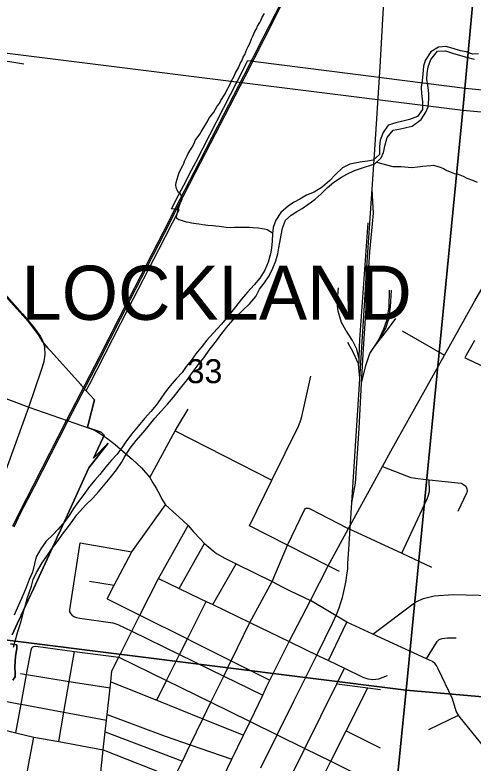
# Model space of a CAD drawing. Extents: x 0 to 34, y -3.9 to 26.2.
# Drawn here: x 3.391 to 4.192, y 19.139 to 20.448 of the extents above; entities that cross this region are included whole.
import ezdxf

# ---------------------------------------------------------------- set-up
doc = ezdxf.new("R2010")
doc.units = 0
for name, color, linetype in [('GM_X_City_Street', 7, 'Continuous'), ('GM_X_Corporation', 7, 'Continuous'), ('GM_X_Corporation_Text', 7, 'Continuous'), ('GM_X_County_Road', 7, 'Continuous'), ('GM_X_Interchange_Ramps', 7, 'Continuous'), ('GM_X_Minor_River', 7, 'Continuous'), ('GM_X_Rail_Line', 7, 'Continuous'), ('GM_X_Section', 7, 'Continuous'), ('GM_X_Section_Text', 7, 'Continuous'), ('GM_X_State_Shield', 7, 'Continuous'), ('GM_X_US_Route', 7, 'Continuous')]:
    doc.layers.add(name, color=color, linetype=linetype)

msp = doc.modelspace()

# ---------------------------------------------------------------- linework, layer by layer
at = {"layer": 'GM_X_City_Street'}
for p, q in [((4.0681, 19.8952), (4.1418, 19.8529)), ((3.3597, 19.61), (3.4148, 19.7617)), ((3.6706, 19.7205), (3.84, 19.6339)), ((3.5049, 19.5244), (3.5948, 19.5084)), ((3.6777, 19.4447), (3.722, 19.5232)), ((3.7366, 19.4163), (3.7778, 19.4875)), ((3.521, 19.4572), (3.5642, 19.4502)), ((3.9392, 19.3185), (3.9713, 19.3857)), ((4.1147, 19.1976), (4.1666, 19.2228)), ((3.5484, 19.1936), (3.6834, 19.1427)), ((3.9699, 19.1953), (4.0293, 19.1657))]:
    msp.add_line(p, q, dxfattribs=at)
for points in [[(3.4148, 19.7617), (3.4368, 19.8271), (3.4416, 19.8416), (3.4433, 19.8548), (3.4426, 19.866)], [(3.8011, 19.5541), (3.84, 19.6339), (3.8864, 19.7288), (3.8912, 19.7408), (3.8955, 19.7585), (3.9083, 19.8163)], [(3.3007, 19.802), (3.3616, 19.7815), (3.4148, 19.7617)], [(3.4148, 19.7617), (3.5219, 19.7242), (3.5312, 19.7208), (3.5369, 19.7176), (3.5437, 19.7128), (3.5509, 19.7081)], [(3.6266, 19.6385), (3.6706, 19.7205), (3.6764, 19.7301), (3.6933, 19.7582)], [(3.5509, 19.7081), (3.5661, 19.6967), (3.5799, 19.6842), (3.5955, 19.6711), (3.6118, 19.6559), (3.6266, 19.6385), (3.632, 19.6297), (3.6378, 19.6199), (3.6432, 19.6094), (3.6473, 19.6006), (3.6541, 19.5911), (3.6669, 19.579), (3.6772, 19.5701), (3.6933, 19.5547), (3.7028, 19.5438), (3.7144, 19.5316), (3.722, 19.5232), (3.7372, 19.5102), (3.7433, 19.5055), (3.7575, 19.4979), (3.7778, 19.4875), (3.8403, 19.4566), (3.857, 19.4482)], [(4.0332, 19.6577), (4.0757, 19.6417), (4.0832, 19.6389), (4.0953, 19.637), (4.115, 19.6348), (4.1709, 19.6286), (4.1735, 19.6276), (4.1754, 19.6265), (4.1776, 19.6249), (4.1791, 19.6234), (4.1803, 19.6209), (4.1809, 19.6188), (4.1813, 19.6157), (4.1811, 19.6127), (4.1806, 19.6112), (4.1651, 19.579)], [(4.067, 19.5061), (4.1114, 19.6017), (4.1131, 19.6058), (4.1159, 19.6141), (4.115, 19.6348)], [(3.5517, 19.4263), (3.5642, 19.4502), (3.5948, 19.5084), (3.6541, 19.5911)], [(3.7643, 19.3091), (3.7687, 19.318), (3.8013, 19.3851), (3.8403, 19.4566), (3.8671, 19.5205), (3.897, 19.5819), (3.8983, 19.5837), (3.8991, 19.5845), (3.8997, 19.5849)], [(3.8997, 19.5849), (3.9018, 19.5853), (3.9029, 19.5853), (3.9036, 19.5851), (3.9069, 19.584), (3.9723, 19.5501), (3.9742, 19.5493), (4.067, 19.5061), (4.119, 19.4819)], [(3.5449, 19.1623), (3.5484, 19.1936), (3.5507, 19.2144), (3.5518, 19.2241), (3.557, 19.2709), (3.5581, 19.2811), (3.5602, 19.3004), (3.5723, 19.3244), (3.5952, 19.3698), (3.6093, 19.3976), (3.6418, 19.4621), (3.6933, 19.5547)], [(3.9583, 19.474), (3.9387, 19.484), (3.8671, 19.5205), (3.8011, 19.5541)], [(3.491, 19.3972), (3.489, 19.4), (3.4869, 19.4036), (3.4866, 19.4054), (3.4865, 19.4073), (3.5049, 19.5244)], [(3.6418, 19.4621), (3.6777, 19.4447), (3.714, 19.4272), (3.7249, 19.4219), (3.7366, 19.4163), (3.8013, 19.3851), (3.8701, 19.3518), (3.9215, 19.327), (3.9392, 19.3185), (3.9672, 19.305), (3.9991, 19.2895), (4.0078, 19.2866), (4.0165, 19.2856), (4.0271, 19.2865), (4.0421, 19.2922)], [(3.857, 19.4482), (3.8721, 19.4407), (3.9077, 19.4237)], [(3.5517, 19.4263), (3.6093, 19.3976), (3.6922, 19.3562), (3.699, 19.3528), (3.7432, 19.3307)], [(4.0164, 19.3649), (4.0916, 19.4215), (4.1051, 19.4272), (4.1238, 19.4316), (4.1572, 19.4341), (4.2023, 19.4327), (4.2372, 19.4316), (4.2485, 19.4287), (4.2785, 19.4187), (4.4519, 19.3613), (4.4663, 19.3606), (4.4834, 19.3624), (4.5054, 19.3622), (4.5311, 19.3555), (4.5363, 19.3541), (4.5575, 19.3517), (4.576, 19.3508), (4.5859, 19.3508), (4.6386, 19.3507), (4.6468, 19.3506)], [(3.6386, 19.2489), (3.6558, 19.2834), (3.6786, 19.329), (3.6922, 19.3562), (3.7249, 19.4219)], [(3.491, 19.3972), (3.4948, 19.395), (3.4967, 19.3941), (3.4985, 19.3936), (3.5041, 19.3926), (3.562, 19.3847), (3.5707, 19.3818), (3.5952, 19.3698), (3.6786, 19.329), (3.7557, 19.2914), (3.8239, 19.258)], [(4.1102, 19.3217), (4.1289, 19.3517), (4.1311, 19.3542), (4.1328, 19.3554), (4.138, 19.3573), (4.1473, 19.3585), (4.1621, 19.3585)], [(3.3923, 19.1922), (3.4014, 19.2419), (3.4109, 19.2939), (3.4187, 19.3368), (3.4201, 19.3407), (3.4221, 19.3425)], [(3.4221, 19.3425), (3.4236, 19.3432), (3.4272, 19.3434), (3.4948, 19.3345), (3.5723, 19.3244), (3.6558, 19.2834), (3.7334, 19.2455), (3.8018, 19.2119), (3.8977, 19.1646), (3.9431, 19.1423), (3.9923, 19.118), (4.0492, 19.09), (4.0704, 19.0795)], [(3.4673, 19.1766), (3.4763, 19.2281), (3.4857, 19.2821), (3.4948, 19.3345)], [(3.7432, 19.3307), (3.7678, 19.3184), (3.7687, 19.318), (3.8366, 19.2841)], [(3.6691, 19.1134), (3.6834, 19.1427), (3.6972, 19.1712), (3.7193, 19.2166), (3.7334, 19.2455), (3.7557, 19.2914), (3.7621, 19.3046), (3.7643, 19.3091)], [(3.4001, 19.2956), (3.4109, 19.2939), (3.4857, 19.2821), (3.557, 19.2709)], [(3.8977, 19.1646), (3.9536, 19.2776), (3.9672, 19.305)], [(3.5581, 19.2811), (3.6386, 19.2489), (3.7193, 19.2166), (3.7904, 19.1882)], [(3.8388, 18.935), (3.8803, 19.0174), (3.9103, 19.0771), (3.9431, 19.1423), (3.9438, 19.1437), (3.9699, 19.1953), (4.0078, 19.2707)], [(3.9536, 19.2776), (4.0078, 19.2707), (4.0301, 19.2678)], [(3.367, 19.2483), (3.3976, 19.2426), (3.4014, 19.2419), (3.4763, 19.2281), (3.5507, 19.2144)], [(3.5518, 19.2241), (3.6533, 19.1863), (3.6972, 19.1712), (3.7702, 19.146)], [(3.4053, 19.0874), (3.4144, 19.1356), (3.4236, 19.1847)], [(3.4926, 18.5849), (3.5025, 18.6997), (3.5108, 18.7976), (3.5115, 18.8047), (3.5134, 18.828), (3.5168, 18.8676), (3.5237, 18.9295), (3.5302, 19.011), (3.5325, 19.0346), (3.5353, 19.0637), (3.5382, 19.0938), (3.54, 19.1119), (3.5417, 19.1292), (3.5449, 19.1623)], [(3.8356, 19.0391), (3.8965, 19.1621), (3.8977, 19.1646)]]:
    msp.add_lwpolyline(points, dxfattribs=at)
at = {"layer": 'GM_X_Corporation'}
for points in [[(3.386, 19.3632), (3.3947, 19.3825), (3.4015, 19.3975), (3.4016, 19.3976), (3.4016, 19.3977), (3.418, 19.4328), (3.4201, 19.4375), (3.4364, 19.4729), (3.4503, 19.5033), (3.4568, 19.5176), (3.4633, 19.5316), (3.4653, 19.536), (3.4673, 19.5404), (3.4853, 19.5796), (3.5201, 19.6554), (3.5535, 19.6989), (3.5281, 19.6728), (3.5441, 19.7076), (3.5465, 19.7129), (3.5412, 19.7178), (3.5272, 19.7228), (3.5176, 19.7262), (3.5189, 19.7315), (3.5297, 19.7747), (3.5154, 19.7906), (3.5182, 19.796), (3.521, 19.8014), (3.5895, 19.9348), (3.6422, 20.0377), (3.6779, 20.1072), (3.6644, 20.1087), (3.6763, 20.1314), (3.691, 20.1603), (3.6961, 20.1701), (3.7071, 20.1905), (3.7799, 20.3326), (3.7981, 20.3683), (3.8113, 20.3666), (4.0185, 20.3402), (4.036, 20.338), (4.1782, 20.3198), (4.2502, 20.3128)], [(3.3557, 19.9761), (3.4101, 19.9157), (3.4153, 19.9092), (3.4298, 19.8903), (3.4353, 19.882), (3.4382, 19.8768), (3.4483, 19.8653), (3.4534, 19.8597), (3.5053, 19.802), (3.5066, 19.8005), (3.5154, 19.7906), (3.5297, 19.7747), (3.5189, 19.7315), (3.5176, 19.7264), (3.5176, 19.7262), (3.5272, 19.7228), (3.5412, 19.7178), (3.5465, 19.7129), (3.5441, 19.7076), (3.5281, 19.6728), (3.5535, 19.6989), (3.5201, 19.6554), (3.4853, 19.5796), (3.4673, 19.5404), (3.4653, 19.536), (3.4633, 19.5316), (3.4568, 19.5176), (3.4503, 19.5033), (3.4364, 19.4729), (3.4201, 19.4375), (3.418, 19.4328), (3.4016, 19.3977), (3.4016, 19.3976), (3.4015, 19.3975), (3.3947, 19.3825), (3.386, 19.3632)], [(4.1944, 19.8782), (4.1892, 19.8691), (4.1846, 19.8609), (4.1799, 19.8526), (4.1773, 19.8481), (4.179, 19.8473), (4.2295, 19.8237)], [(3.3903, 19.3062), (3.3908, 19.3174), (3.3918, 19.3255), (3.3918, 19.3256), (3.3928, 19.333), (3.3937, 19.3392), (3.3939, 19.3402), (3.3941, 19.3459), (3.3826, 19.3475)], [(3.3826, 19.3475), (3.3941, 19.3459), (3.3939, 19.3402), (3.3937, 19.3392), (3.3928, 19.333), (3.3918, 19.3256), (3.3918, 19.3255), (3.3908, 19.3174), (3.3903, 19.3062)], [(3.3872, 19.2843), (3.3911, 19.29), (3.3908, 19.2967), (3.3903, 19.3061)], [(3.3903, 19.3061), (3.3908, 19.2967), (3.3911, 19.29), (3.3872, 19.2843)]]:
    msp.add_lwpolyline(points, dxfattribs=at)
at = {"layer": 'GM_X_County_Road'}
for points in [[(3.2665, 20.3824), (3.3049, 20.3771), (3.3854, 20.3661), (3.4059, 20.3627)], [(3.249, 20.0295), (3.2583, 20.0286), (3.2683, 20.0273), (3.2804, 20.0244), (3.2873, 20.0228), (3.3037, 20.0165), (3.3175, 20.0101), (3.3318, 20.0009), (3.343, 19.9918), (3.3578, 19.9767), (3.363, 19.9705), (3.404, 19.9249), (3.4226, 19.9032), (3.4351, 19.8853), (3.4392, 19.8768), (3.4426, 19.866)], [(4.531, 18.7211), (4.5289, 18.7386), (4.5326, 18.7785), (4.5323, 18.7842), (4.5313, 18.7911), (4.5289, 18.798), (4.5251, 18.8049), (4.5234, 18.8071), (4.4853, 18.8456), (4.4237, 18.9101), (4.3697, 18.9768), (4.2658, 19.0997), (4.169, 19.2187), (4.1666, 19.2228), (4.1624, 19.2298), (4.1556, 19.2516), (4.1308, 19.3038), (4.1279, 19.3099), (4.1253, 19.3129), (4.1209, 19.3168), (4.1102, 19.3217), (4.0164, 19.3649), (3.9713, 19.3857), (3.9077, 19.4237)], [(3.3672, 19.1987), (3.3923, 19.1922), (3.4236, 19.1847), (3.4673, 19.1766), (3.5449, 19.1623), (3.6691, 19.1134), (3.6849, 19.1072), (3.741, 19.0851), (3.8356, 19.0391), (3.8803, 19.0174), (3.8891, 19.0131)]]:
    msp.add_lwpolyline(points, dxfattribs=at)
at = {"layer": 'GM_X_Interchange_Ramps'}
for points in [[(3.3557, 19.9761), (3.4101, 19.9157), (3.4153, 19.9092), (3.4298, 19.8903), (3.4353, 19.882), (3.4382, 19.8768), (3.4483, 19.8653), (3.4534, 19.8597), (3.5053, 19.802), (3.5066, 19.8005), (3.5154, 19.7906), (3.5182, 19.796), (3.5182, 19.796), (3.521, 19.8014), (3.5895, 19.9348), (3.6422, 20.0377), (3.6779, 20.1072), (3.6644, 20.1087), (3.6763, 20.1314), (3.691, 20.1603), (3.6961, 20.17), (3.7071, 20.1905), (3.7799, 20.3326), (3.7981, 20.3683), (3.8113, 20.3666), (4.0185, 20.3402), (4.036, 20.338), (4.1782, 20.3198), (4.2502, 20.3128)], [(4.1944, 19.8782), (4.1892, 19.8691), (4.1846, 19.8609), (4.1799, 19.8526), (4.1773, 19.8481), (4.179, 19.8473), (4.2295, 19.8237)]]:
    msp.add_lwpolyline(points, dxfattribs=at)
at = {"layer": 'GM_X_Minor_River'}
for points in [[(3.8408, 20.0661), (3.8317, 20.072), (3.8268, 20.0733), (3.823, 20.0739), (3.8166, 20.0749), (3.8071, 20.0753), (3.8007, 20.0759), (3.7965, 20.0761), (3.7885, 20.0761), (3.7836, 20.0759), (3.7748, 20.0759), (3.768, 20.0758), (3.76, 20.0761), (3.7562, 20.0766), (3.7521, 20.0772), (3.7475, 20.0778), (3.7418, 20.0784), (3.7366, 20.079), (3.7278, 20.0797), (3.7241, 20.0802), (3.7184, 20.0809), (3.7123, 20.0819), (3.7078, 20.0824), (3.6995, 20.0839), (3.695, 20.0849), (3.6904, 20.0854), (3.6822, 20.0881), (3.6773, 20.0894), (3.6736, 20.0918), (3.6734, 20.096), (3.6769, 20.1092), (3.6783, 20.1145), (3.6805, 20.1212), (3.6829, 20.1249), (3.6827, 20.1302), (3.6802, 20.1345), (3.6765, 20.1373), (3.6744, 20.1416), (3.6727, 20.1459), (3.6721, 20.1508), (3.6727, 20.1546), (3.6779, 20.1726), (3.6837, 20.1834), (3.6857, 20.1879), (3.6871, 20.1924), (3.692, 20.2017), (3.6937, 20.2054), (3.7006, 20.2169), (3.7038, 20.2229), (3.7056, 20.2285), (3.714, 20.2392), (3.7161, 20.2433), (3.7246, 20.257), (3.7278, 20.2626), (3.7295, 20.267), (3.7387, 20.2781), (3.7444, 20.2885), (3.7484, 20.2933), (3.7509, 20.2985), (3.7582, 20.31), (3.7599, 20.3141), (3.7664, 20.326), (3.7681, 20.3304), (3.7747, 20.342), (3.776, 20.3457), (3.7821, 20.3569), (3.7846, 20.3632), (3.7875, 20.368), (3.7896, 20.3744), (3.7928, 20.3788), (3.7963, 20.3882), (3.7987, 20.393), (3.8012, 20.3983), (3.8042, 20.4061), (3.8058, 20.4099), (3.8087, 20.4151), (3.81, 20.4192), (3.8129, 20.424), (3.8146, 20.4285), (3.819, 20.4348), (3.8207, 20.4385), (3.8228, 20.4441), (3.8272, 20.4508)], [(4.2014, 20.3801), (4.1916, 20.3796), (4.1795, 20.3832), (4.1697, 20.3853), (4.1572, 20.3893), (4.1444, 20.393), (4.1315, 20.3917), (4.1177, 20.3832), (4.1083, 20.3682), (4.1054, 20.3584), (4.104, 20.3451), (4.1027, 20.3329), (4.1013, 20.3219), (4.1019, 20.3102), (4.1035, 20.2964), (4.1032, 20.2828), (4.0947, 20.2704), (4.0809, 20.2653), (4.0691, 20.2621), (4.0569, 20.2593), (4.0435, 20.2554), (4.0349, 20.2422), (4.0294, 20.229), (4.0284, 20.2176), (4.0282, 20.204), (4.017, 20.1939), (4.0071, 20.1922), (3.9976, 20.1912), (3.988, 20.1895), (3.9766, 20.1867), (3.9636, 20.1808), (3.9512, 20.1689), (3.9412, 20.1585), (3.9277, 20.1469), (3.9138, 20.1381), (3.9005, 20.1326), (3.8886, 20.126), (3.879, 20.1205), (3.869, 20.1138), (3.8559, 20.1023), (3.8469, 20.0888), (3.8421, 20.0759), (3.8408, 20.0657), (3.8405, 20.0524), (3.8395, 20.0398), (3.8378, 20.03)], [(3.8266, 19.9789), (3.8352, 19.9916), (3.8419, 20.0052), (3.8471, 20.0177), (3.8503, 20.0298), (3.8524, 20.0404), (3.8538, 20.0498), (3.8563, 20.0627), (3.8588, 20.0748), (3.864, 20.0888), (3.8736, 20.0978), (3.8836, 20.1044), (3.8932, 20.1096), (3.9028, 20.1162), (3.9159, 20.1255), (3.9259, 20.1352), (3.9364, 20.1456), (3.9483, 20.1553), (3.9618, 20.1641), (3.9713, 20.1697), (3.9847, 20.1759), (3.9947, 20.1795), (4.0199, 20.1874), (4.0311, 20.1978), (4.0354, 20.2076), (4.0383, 20.2205), (4.0416, 20.2337), (4.0521, 20.2465), (4.0647, 20.2489), (4.0749, 20.251), (4.0852, 20.2534), (4.101, 20.2653), (4.1092, 20.2777), (4.1132, 20.2875), (4.1146, 20.3008), (4.1144, 20.3103), (4.1131, 20.3213), (4.1111, 20.3355), (4.1113, 20.3457), (4.1134, 20.3571), (4.1182, 20.3703), (4.1298, 20.3845), (4.1435, 20.385), (4.1559, 20.3814), (4.1699, 20.3773), (4.1805, 20.3744), (4.1937, 20.3704)], [(4.023, 20.1903), (4.0515, 20.1826), (4.0659, 20.1828), (4.0728, 20.1821), (4.0784, 20.1815), (4.0849, 20.1813), (4.0948, 20.182), (4.104, 20.1835), (4.1173, 20.1849), (4.1226, 20.185), (4.1283, 20.1836), (4.1343, 20.1819), (4.1399, 20.1794), (4.1462, 20.1761), (4.1533, 20.1727), (4.1586, 20.1706), (4.1657, 20.1692), (4.1743, 20.1662), (4.1807, 20.1625), (4.1908, 20.159), (4.199, 20.1556)], [(3.8378, 20.03), (3.8337, 20.0152), (3.8278, 20.0013), (3.8188, 19.9874), (3.8091, 19.9758), (3.7971, 19.9631), (3.7866, 19.9507), (3.7761, 19.9373), (3.7656, 19.9241), (3.7517, 19.9073), (3.7377, 19.892), (3.7261, 19.8789), (3.7183, 19.8688), (3.707, 19.8549), (3.6989, 19.8437), (3.6899, 19.8328), (3.6829, 19.8223), (3.6725, 19.8111), (3.662, 19.7991), (3.6534, 19.7883), (3.6445, 19.7751), (3.6378, 19.7654), (3.6285, 19.7545), (3.6173, 19.7418), (3.6064, 19.7287), (3.5947, 19.7145), (3.5846, 19.701), (3.5776, 19.6905), (3.5687, 19.6788), (3.5597, 19.6691), (3.5497, 19.6572), (3.5388, 19.6437), (3.5306, 19.6339), (3.5209, 19.6231), (3.5112, 19.6092), (3.5015, 19.5965), (3.4929, 19.5845), (3.4855, 19.5725), (3.4777, 19.562), (3.466, 19.5485), (3.4567, 19.5384), (3.4455, 19.5272), (3.4358, 19.5137), (3.4279, 19.4998), (3.4251, 19.4877), (3.4214, 19.4733), (3.4154, 19.4601), (3.4102, 19.4461), (3.4059, 19.4363), (3.3995, 19.422), (3.3944, 19.4099), (3.3892, 19.3979)], [(3.3878, 19.342), (3.3918, 19.3549), (3.3959, 19.3692), (3.3991, 19.3798), (3.4024, 19.3912), (3.4061, 19.4059), (3.4097, 19.4176), (3.4126, 19.429), (3.4162, 19.4388), (3.4194, 19.4486), (3.4223, 19.4604), (3.4286, 19.4728), (3.4384, 19.4897), (3.4477, 19.5028), (3.4544, 19.5134), (3.466, 19.5287), (3.4738, 19.5396), (3.484, 19.5531), (3.4917, 19.5636), (3.4991, 19.5733), (3.5142, 19.5902), (3.5266, 19.6025), (3.5367, 19.6137), (3.5456, 19.6242), (3.5569, 19.638), (3.5682, 19.6522), (3.5767, 19.665), (3.583, 19.6752), (3.5924, 19.6902), (3.6029, 19.7033), (3.6157, 19.7183), (3.6235, 19.728), (3.6355, 19.7426), (3.6463, 19.7546), (3.6572, 19.7673), (3.6681, 19.7792), (3.6778, 19.7924), (3.6925, 19.81), (3.7007, 19.822), (3.7109, 19.8358), (3.721, 19.8482), (3.7322, 19.8636), (3.7431, 19.8778), (3.7525, 19.8906), (3.7638, 19.9048), (3.7762, 19.9194), (3.7881, 19.9306), (3.8013, 19.9432), (3.8121, 19.9556), (3.8181, 19.968), (3.8266, 19.9789)]]:
    msp.add_lwpolyline(points, dxfattribs=at)
at = {"layer": 'GM_X_Rail_Line'}
for p, q in [((4.0196, 19.8681), (4.0271, 19.8796)), ((3.992, 19.8307), (3.9926, 19.8455)), ((3.9937, 19.8124), (3.992, 19.8307))]:
    msp.add_line(p, q, dxfattribs=at)
for points in [[(4.0057, 19.9984), (4.0196, 20.2035), (4.0292, 20.3575), (4.0342, 20.4404), (4.0389, 20.5215), (4.0398, 20.5338)], [(3.3868, 19.5538), (3.3989, 19.5787), (3.4223, 19.6242), (3.481, 19.7387), (3.5378, 19.8485), (3.5904, 19.9517), (3.6499, 20.0676), (3.6717, 20.1098), (3.7045, 20.1744), (3.7558, 20.2741), (3.7908, 20.3416), (3.8242, 20.407), (3.8571, 20.4717)], [(3.389, 19.5527), (3.4011, 19.5776), (3.4246, 19.6231), (3.4832, 19.7375), (3.54, 19.8473), (3.5926, 19.9505), (3.6521, 20.0665), (3.6739, 20.1087), (3.7067, 20.1733), (3.758, 20.2729), (3.793, 20.3405), (3.8264, 20.4058), (3.8593, 20.4705)], [(3.9967, 19.804), (4, 19.8638), (4.0115, 20.0336), (4.016, 20.0823), (4.0175, 20.101), (4.0154, 20.1428)], [(3.9926, 19.8455), (3.9928, 19.8502), (3.994, 19.8804), (4.0086, 20.0843)], [(3.8208, 19.1305), (3.8785, 19.2477), (3.9209, 19.3328), (3.946, 19.3837), (3.9538, 19.4001), (3.9579, 19.411), (3.9608, 19.4202), (3.9633, 19.4287), (3.9661, 19.4392), (3.9683, 19.4495), (3.9699, 19.4586), (3.9713, 19.4679), (3.9726, 19.4787), (3.9731, 19.4884), (3.9747, 19.5135), (3.9829, 19.64), (3.9913, 19.7749), (4.0036, 19.9675), (4.0057, 19.9984)], [(3.9926, 19.8455), (3.9883, 19.8634), (3.9809, 19.8784), (3.9692, 19.8965), (3.9616, 19.91), (3.956, 19.9296), (3.954, 19.9437), (3.9564, 19.9703)], [(4.0271, 19.8796), (4.0355, 19.8987), (4.0411, 19.9133), (4.0452, 19.9368), (4.0458, 19.9664)], [(4.0271, 19.8796), (4.039, 19.9002), (4.0448, 19.9164), (4.0477, 19.9372), (4.0493, 19.9664)], [(4.0196, 19.8681), (4.0421, 19.8969), (4.0569, 19.9168)], [(3.992, 19.8307), (3.9914, 19.8379), (3.9829, 19.8568), (3.9731, 19.8747)], [(3.9967, 19.804), (4.0043, 19.8348), (4.0115, 19.8556), (4.0196, 19.8681)], [(3.9799, 19.5944), (3.986, 19.6287), (3.9924, 19.7247), (3.9967, 19.804)]]:
    msp.add_lwpolyline(points, dxfattribs=at)
at = {"layer": 'GM_X_Section'}
for points in [[(3.1493, 20.4095), (4.1738, 20.2814), (4.0751, 19.2669), (3.0608, 19.3936), (3.0628, 19.4174)], [(4.1738, 20.2814), (5.1778, 20.1897), (5.0852, 19.1785), (4.0751, 19.2669)], [(3.0608, 19.3936), (4.0751, 19.2669), (3.9744, 18.2676), (2.9569, 18.3849)], [(4.0751, 19.2669), (5.0852, 19.1785), (4.9898, 18.1753), (3.9744, 18.2676)]]:
    msp.add_lwpolyline(points, close=True, dxfattribs=at)
at = {"layer": 'GM_X_State_Shield'}
for points in [[(4.2313, 20.9), (3.1968, 20.9), (3.1493, 20.4095), (4.1738, 20.2814)], [(5.2454, 20.9), (4.2313, 20.9), (4.1738, 20.2814), (5.1778, 20.1897)]]:
    msp.add_lwpolyline(points, close=True, dxfattribs=at)
at = {"layer": 'GM_X_US_Route'}
msp.add_lwpolyline([(3.741, 19.0851), (3.7702, 19.146), (3.7904, 19.1882), (3.8018, 19.2119), (3.8239, 19.258), (3.8314, 19.2736), (3.8366, 19.2841), (3.8701, 19.3518), (3.9077, 19.4237), (3.9387, 19.484), (3.9742, 19.5493), (4.0332, 19.6577), (4.048, 19.685), (4.1418, 19.8529), (4.1951, 19.9481), (4.2198, 19.9911)], dxfattribs=at)

# ---------------------------------------------------------------- texts
at = {"layer": 'GM_X_Corporation_Text'}
msp.add_text('LOCKLAND', height=0.0947, rotation=0, dxfattribs=at).set_placement((3.402, 19.9146))
at = {"layer": 'GM_X_Section_Text'}
msp.add_text('33', height=0.04186, rotation=0, dxfattribs=at).set_placement((3.691, 19.8038))

doc.saveas('drawing.dxf')
